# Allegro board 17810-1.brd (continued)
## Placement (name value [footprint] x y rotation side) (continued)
EC8927  SC1U50V3KX-GP  [C603H32]  122.2 108.6 0 top
EC8928  SC1U50V3KX-GP  [C603H32]  140.59 107.84 0 top
EC8929  SC1U50V3KX-GP  [C603H32]  157.4 58.64 90 top
EC8930  SCD1U25V2KX-GP  [C402H22]  35.36 90.26 270 top
EC8931  SCD1U25V2KX-GP  [C402H22]  149.66 104.87 180 bottom
EC8932  SCD1U25V2KX-GP  [C402H22]  161.97 63.85 270 bottom
EC8933  SC2200P50V2KX-2GP  [C402H22]  75.92 52.84 0 top
EC8934  SC2200P50V2KX-2GP  [C402H22]  76.81 52.84 0 top
EC8935  SC2200P50V2KX-2GP  [C402H22]  77.67 52.84 0 top
EC8936  SCD1U25V2KX-GP  [C402H22]  78.56 52.84 0 top
EC8937  SCD1U25V2KX-GP  [C402H22]  79.43 52.83 0 top
EC8938  SCD1U25V2KX-GP  [C402H22]  80.31 52.83 0 top
EC8939  SCD1U25V2KX-GP  [C402H22]  65.71 99.53 0 top
EC8940  SCD1U25V2KX-GP  [C402H22]  167.56 89.5 90 bottom
EC8941  SCD1U25V2KX-GP  [C402H22]  153.08 52.04 180 top
EC8942  SCD1U25V2KX-GP  [C402H22]  166.8 87.47 270 top
EC8943  SCD1U25V2KX-GP  [C402H22]  159.69 70.07 180 top
EC8944  SCD1U25V2KX-GP  [C402H22]  169.34 52.92 90 top
EC8945  SCD1U25V2KX-GP  [C402H22]  44.12 98.9 90 top
EC8946  SCD1U25V2KX-GP  [C402H22]  162.23 80.74 270 top
EC8947  SCD1U25V2KX-GP  [C402H22]  51.48 99.79 90 top
EC8948  SCD1U25V2KX-GP  [C402H22]  71.93 99.03 0 top
EC8949  SCD1U25V2KX-GP  [C402H22]  171.88 79.85 90 top
EC8950  SCD1U25V2KX-GP  [C402H22]  163.5 70.96 90 bottom
EC8951  SCD1U25V2KX-GP  [C402H22]  162.61 80.61 90 bottom
EC8952  SCD1U25V2KX-GP  [C402H22]  164.51 103.72 90 bottom
EC8953  SCD1U25V2KX-GP  [C402H22]  174.04 28.92 90 bottom
EC8954  SCD1U25V2KX-GP  [C402H22]  167.56 88.74 90 bottom
EC8955  SCD1U25V2KX-GP  [C402H22]  157.02 107.66 0 top
ED401  AZ5725-01FDR7G-GP  [SOD882-10D6-1H20]  131.11 75.15 270 bottom
ED501  AZ5725-01FDR7G-GP  [SOD882-10D6-1H20]  88.44 17.36 90 top
ED1217  AZ5725-01FDR7G-GP  [SOD882-10D6-1H20]  48.61 60.29 0 top
ED1302  AZ5725-01FDR7G-GP  [SOD882-10D6-1H20]  47.72 60.29 0 top
ED1701  AZ5725-01FDR7G-GP  [SOD882-10D6-1H20]  133.91 77.31 0 bottom
ED1702  AZ5725-01FDR7G-GP  [SOD882-10D6-1H20]  123.49 37.94 270 top
ED1703  AZ5725-01FDR7G-GP  [SOD882-10D6-1H20]  113.49 22.14 270 bottom
ED1704  AZ5725-01FDR7G-GP  [SOD882-10D6-1H20]  103.1 20.03 0 bottom
ED1705  AZ5725-01FDR7G-GP  [SOD882-10D6-1H20]  149.91 16.22 180 top
ED1708  AZ5725-01FDR7G-GP  [SOD882-10D6-1H20]  104.24 93.82 0 bottom
ED1709  AZ5725-01FDR7G-GP  [SOD882-10D6-1H20]  106.6 95.47 0 bottom
ED1711  AZ5725-01FDR7G-GP  [SOD882-10D6-1H20]  103.96 20.03 0 bottom
ED2401  AZ5725-01FDR7G-GP  [SOD882-10D6-1H20]  189.23 39.69 180 bottom
ED2901  DF2B6D8E-1-GP  [D1608AK-UH28]  16.43 12.34 0 top
ED2902  AZ5725-01FDR7G-GP  [SOD882-10D6-1H20]  17.19 10.41 180 bottom
ED2903  AZ5725-01FDR7G-GP  [SOD882-10D6-1H20]  16.97 22.29 90 top
ED2904  AZ5725-01FDR7G-GP  [SOD882-10D6-1H20]  17.37 23.44 90 top
ED2905  AZ5725-01FDR7G-GP  [SOD882-10D6-1H20]  18.18 24.55 90 top
ED2906  DF2B6D8E-1-GP  [D1608AK-UH28]  18.21 12.34 0 top
ED3601  L05ESDL5V0NA-4-GP  [SLP2510P8-1H22]  19.41 53.31 90 top
ED3602  AZC099-04S-1-GP  [SOT-6H58]  20.32 53.23 90 bottom
ED3603  L05ESDL5V0NA-4-GP  [SLP2510P8-1H22]  19.23 31.08 90 top
ED3801  AZ5315-02F-GP  [SOT883-1D0-321H20]  19.61 41.88 90 top
ED3802  L05ESDL5V0NA-4-GP  [SLP2510P8-1H22]  14.35 98.52 90 top
ED3803  AZ5315-02F-GP  [SOT883-1D0-321H20]  16.56 95.98 180 top
ED3804  AZ5315-02F-GP  [SOT883-1D0-321H20]  16.71 93.72 270 top
ED3805  AZ5315-02F-GP  [SOT883-1D0-321H20]  13.99 94.45 270 top
ED3806  L05ESDL5V0NA-4-GP  [SLP2510P8-1H22]  14.3 91.84 90 top
ED6305  PESD5V0U1BL-GP-U1  [SOD882-10D6-1H20]  197.28 24.1 0 top
ED6401  PESD5V0S1BB-GP-U  [SOD-523-2H26]  67.74 8.4 180 bottom
ED6402  PESD5V0S1BB-GP-U  [SOD-523-2H26]  54.53 3.52 180 bottom
EL2901  HCB1005KF-121T20-GP  [L402H24]  18.59 8.22 270 top
EL2902  HCB1005KF-121T20-GP  [L402H24]  18.21 9.64 270 top
EL2903  HCB1005KF-121T20-GP  [L402H24]  18.21 4.41 270 top
EL2904  HCB1005KF-121T20-GP  [L402H24]  17.32 3.01 270 top
EL3605  COIL-90OHM-100MHZ-5-GP  [L125100-4P-4H24]  22.4 50.23 90 bottom
EL3606  COIL-90OHM-100MHZ-5-GP  [L125100-4P-4H24]  24.1 52.34 90 bottom
EL3801  COIL-90OHM-100MHZ-5-GP  [L125100-4P-4H24]  37.36 36.08 180 top
EL3802  COIL-90OHM-100MHZ-5-GP  [L125100-4P-4H24]  45.34 37.13 90 top
EL4301  0R5J-5-GP  [R805H24]  22.78 84.17 0 top
EL4302  0R5J-5-GP  [R805H24]  24.69 84.17 0 top
EL4303  0R5J-5-GP  [R805H24]  17.19 81.65 270 top
EL4304  0R5J-5-GP  [R805H24]  17.19 79.85 270 top
EL5501  COIL-90OHM-100MHZ-5-GP  [L125100-4P-4H24]  64.95 91.53 180 top
EL5502  COIL-90OHM-100MHZ-5-GP  [L125100-4P-4H24]  73.2 92.19 180 top
EL6601  COIL-90OHM-100MHZ-5-GP  [L125100-4P-4H24]  172.29 49.98 0 top
EL6602  COIL-90OHM-100MHZ-5-GP  [L125100-4P-4H24]  172.29 47.35 0 top
EL6603  COIL-90OHM-100MHZ-5-GP  [L125100-4P-4H24]  172.41 52.44 0 top
F5501  POLYSW-1D1A6V-9-GP-U  [POLYSW-2114H30]  69.14 98.52 0 top
F5502  POLYSW-1D1A6V-9-GP-U  [POLYSW-2114H30]  55.88 99.2 180 top
F5503  POLYSW-1D1A24V-GP-U  [POLYSW-4633-UH43]  74.73 97.12 0 top
F5504  POLYSW-1D1A6V-9-GP-U  [POLYSW-2114H30]  56.79 96.21 270 top
F5701  POLYSW-1D1A6V-9-GP-U  [POLYSW-2114H30]  21.94 58.46 270 top
F6501  POLYSW-1D1A6V-9-GP-U  [POLYSW-2114H30]  151.56 10.63 90 bottom
FAN1  ACES-CON4-29-GP  [50224-0040N-001]  159.96 75.71 270 bottom
G1801  GAP-OPEN  [CON2O-U]  74.73 16.7 270 top
GMR1  HGDEDM013A-GP  [OPLGA4-0913H22]  7.26 85.48 180 top
GPU1  UNI-CONN48-6R-GP-U2  [XBGCB5009-U2]  174.7 89.86 270 bottom
GPU2  UNI-CONN28-6R-GP-U  [XBGCB5008]  174.7 75.98 90 bottom
H2  HOLE335R178-GP  [HOLE335R178]  175.7 101.21 180 bottom
H3  HOLE335R229-GP  [HOLE335R229]  162 39.06 180 bottom
H4  HOLE335R178-GP  [HOLE335R178]  188.47 21.41 180 bottom
H5  HOLE335R229-GP  [HOLE335R229]  115.9 3.99 180 bottom
H6  HOLE335R229-GP  [HOLE335R229]  25.9 3.99 180 bottom
H7  HOLE335R178-GP  [HOLE335R178]  128.85 84.21 180 bottom
H8  HOLE335R178-GP  [HOLE335R178]  102.85 84.21 180 bottom
H9  HOLE335R178-GP  [HOLE335R178]  128.85 29.21 180 bottom
H10  HOLE335R178-GP  [HOLE335R178]  102.85 29.21 180 bottom
HDA27  ALC3253-VA3-CG-GP  [QFN48J6-G465H40]  23.75 17.11 270 top
HDD1  FOX-CON20-1-GP-U1  [GS12201-1011-9H]  180.52 19.83 90 bottom
HDMI1  SKT-HDMI23-167-GP-U  [SKT-HDMI23-188137-4]  4.6 74.58 90 bottom
HPMIC1  AUDIO-JK522-GP  [AJ3R2D-Y050-412]  4.2 17.09 90 bottom
HS1  STF217R115H101-2-GP  [STF217R115H101]  10.8 86.51 180 bottom
HS2  STFSR158R113H62-GP  [STFSR158R113H62]  174.7 89.86 0 top
HS3  STFSR158R113H62-GP  [STFSR158R113H62]  174.7 75.98 0 top
IOBD1  IPEX-CON50-1-GP  [20455-050E-76]  171.7 46.46 270 bottom
KB1  PTWO-CON30-18-GP  [196528-30041-3]  83.72 6.21 180 bottom
KBBL1  ACES-CON4-90-GP-U  [50698-00401-W01-U]  105.76 4.31 180 bottom
KBC24  MEC1416-NU-D0-GP  [TQFP128-2H48]  191.01 36.44 270 top
L3801  BLM15AX221SN1D-GP  [L402H22]  25.25 61.69 90 top
LCD1  IPEX-CON40-3-GP  [20455-040E-12]  88.7 97.71 0 bottom
LED1  ACES-CON4-66-GP  [50524-00401-001]  60.94 7.61 180 bottom
NOREF  -  []  -24.49 -18.4 0 top
NOREF#2  -  []  46.07 3.73 0 top
NOREF#3  -  [unnamed#2]  234.17 -111.51 0 top
NOREF#4  -  []  136.83 94.71 0 top
NOREF#5  -  [unnamed#2]  207.95 -110.43 0 top
NOREF#6  -  [unnamed#2]  234.17 78.88 0 top
NOREF#7  -  []  226.91 47.72 0 top
NOREF#8  -  [unnamed#2]  24.4 108.43 180 top
NOREF#9  -  []  130.55 110.71 0 top
NOREF#10  -  [unnamed#2]  -1.83 109.52 0 top
NOREF#11  -  []  8.38 114.65 180 top
NOREF#12  -  []  1.7 -16.29 0 top
NOREF#13  -  [unnamed#2]  4.44 4 0 top
NOREF#14  -  []  238.35 95.88 270 top
NOREF#15  -  []  218.92 -116.72 0 top
NOREF#16  -  []  82.45 78.17 0 top
NOREF#17  -  []  159.95 -115.38 180 top
NOREF#18  -  [unnamed#2]  233.6 15.21 180 top
NOREF#19  -  [unnamed#2]  -1.22 -25.43 0 top
NOREF#20  *  [unnamed#2]  18.76 109.51 0 top
NOREF#21  -  [unnamed#2]  -1.82 -80.88 0 top
NOREF#22  -  []  1.7 -16.29 0 top
NOREF#23  -  [unnamed#2]  169.35 102.57 0 top
NOREF#24  -  []  1.7 -16.29 0 top
NOREF#25  *  [unnamed#2]  229.22 -111.51 0 top
NOREF#26  -  []  10.06 -11.34 270 top
NOREF#27  -  []  72.4 113.39 0 top
NOREF#28  *  [unnamed#2]  4.88 7.66 0 top
NOREF#29  *  [unnamed#2]  198.3 7.71 0 top
NOREF#30  -  []  1.7 -16.29 0 top
NOREF#31  -  []  5.44 -49.72 180 top
NOREF#32  -  []  182.85 -4.96 180 top
NOREF#33  *  [unnamed#2]  232.84 113.08 0 top
NOREF#34  *  [unnamed#2]  18.76 109.51 180 bottom
NOREF#35  -  []  86.92 26.25 180 bottom
NOREF#36  -  []  86.28 105.38 180 bottom
NOREF#37  -  []  10.06 -28.1 90 bottom
NOREF#38  *  [unnamed#2]  203.12 7.89 180 bottom
NOREF#39  -  []  218.24 17.62 180 bottom
NOREF#40  -  []  18.97 -19.08 180 bottom
NOREF#41  -  []  178.1 46.07 180 bottom
NOREF#42  *  [unnamed#2]  17.24 99.2 180 bottom
NOREF#43  *  [unnamed#2]  136.4 16.04 180 bottom
NOREF#44  -  []  38.4 78.45 180 bottom
NOREF#45  *  [unnamed#2]  95.25 89.35 180 bottom
NOREF#46  *  [unnamed#2]  229.22 -111.51 180 bottom
NOREF#47  *  [unnamed#2]  4.88 7.64 180 bottom
NOREF#48  *  [unnamed#2]  232.84 113.08 180 bottom
NOREF#49  -  []  94.41 111.85 180 bottom
PC1001  SC22U6D3V3MX-1-GP  [C603H40]  126.13 97.73 180 top
PC1002  SC22U6D3V3MX-1-GP  [C603H40]  139.75 76.04 270 bottom
PC1003  SC22U6D3V3MX-1-GP  [C603H40]  140 63.97 0 top
PC1004  SC22U6D3V3MX-1-GP  [C603H40]  141.27 69.31 180 top
PC1005  SC22U6D3V3MX-1-GP  [C603H40]  119.56 56.73 0 top
PC1006  SC22U6D3V3MX-1-GP  [C603H40]  113.87 60.67 180 top
PC1007  SC22U6D3V3MX-1-GP  [C603H40]  139.5 71.21 90 top
PC1008  SC22U6D3V3MX-1-GP  [C603H40]  139.5 76.29 90 top
PC1009  SC22U6D3V3MX-1-GP  [C603H40]  132.76 62.7 180 bottom
PC1010  SC22U6D3V3MX-1-GP  [C603H40]  113.59 53.66 180 top
PC1011  SC22U6D3V3MX-1-GP  [C603H40]  113.21 56.73 0 top
PC1012  SC22U6D3V3MX-1-GP  [C603H40]  115.62 53.66 180 top
PC1013  SC22U6D3V3MX-1-GP  [C603H40]  117.65 53.66 180 top
PC1014  SC22U6D3V3MX-1-GP  [C603H40]  114.48 56.73 0 top
PC1015  SC22U6D3V3MX-1-GP  [C603H40]  115.14 60.67 180 top
PC1016  SC22U6D3V3MX-1-GP  [C603H40]  119.68 53.66 180 top
PC1017  SC22U6D3V3MX-1-GP  [C603H40]  111.94 55.72 0 top
PC1018  SC22U6D3V3MX-1-GP  [C603H40]  135.3 62.7 180 bottom
PC1019  SC22U6D3V3MX-1-GP  [C603H40]  134.03 62.7 180 bottom
PC1020  SC22U6D3V3MX-1-GP  [C603H40]  117.68 63.75 0 top
PC1021  SC22U6D3V3MX-1-GP  [C603H40]  139.5 77.56 90 top
PC1022  SC22U6D3V3MX-1-GP  [C603H40]  141.53 62.7 0 top
PC1023  SC22U6D3V3MX-1-GP  [C603H40]  137.29 63.97 0 top
PC1024  SC22U6D3V3MX-1-GP  [C603H40]  116.41 60.67 180 top
PC1025  SC22U6D3V3MX-1-GP  [C603H40]  117.68 60.67 180 top
PC1026  SC22U6D3V3MX-1-GP  [C603H40]  138.61 63.97 0 top
PC1027  SC22U6D3V3MX-1-GP  [C603H40]  139.75 77.44 270 bottom
PC1028  SC22U6D3V3MX-1-GP  [C603H40]  139.5 73.75 90 top
PC1029  SC22U6D3V3MX-1-GP  [C603H40]  139.5 75.02 90 top
PC1030  SC22U6D3V3MX-1-GP  [C603H40]  139.5 72.48 90 top
PC1031  SC22U6D3V3MX-1-GP  [C603H40]  141.53 62.7 180 bottom
PC1032  SC22U6D3V3MX-1-GP  [C603H40]  142.92 62.7 180 bottom
PC1033  SC22U6D3V3MX-1-GP  [C603H40]  115.14 63.75 0 top
PC1034  SC22U6D3V3MX-1-GP  [C603H40]  142.92 62.7 0 top
PC1035  SC22U6D3V3MX-1-GP  [C603H40]  115.75 56.73 0 top
PC1036  SC22U6D3V3MX-1-GP  [C603H40]  142.54 68.93 180 top
PC1037  SC22U6D3V3MX-1-GP  [C603H40]  118.92 68.42 270 top
PC1038  SC22U6D3V3MX-1-GP  [C603H40]  119.3 76.29 90 top
PC1039  SC22U6D3V3MX-1-GP  [C603H40]  123.59 97.73 180 top
PC1040  SC22U6D3V3MX-1-GP  [C603H40]  133.78 89.37 180 bottom
PC1041  SC22U6D3V3MX-1-GP  [C603H40]  124.43 95.5 0 bottom
PC1042  SC22U6D3V3MX-1-GP  [C603H40]  122.22 89.88 180 bottom
PC1043  SC22U6D3V3MX-1-GP  [C603H40]  118.92 69.69 270 top
PC1044  SC22U6D3V3MX-1-GP  [C603H40]  115.87 70.96 90 top
PC1045  SC22U6D3V3MX-1-GP  [C603H40]  124.76 89.88 180 bottom
PC1046  SC22U6D3V3MX-1-GP  [C603H40]  119.3 73.75 90 top
PC1047  SC22U6D3V3MX-1-GP  [C603H40]  118.92 70.96 270 top
PC1048  SC22U6D3V3MX-1-GP  [C603H40]  128.57 90.14 180 bottom
PC1049  SC22U6D3V3MX-1-GP  [C603H40]  110.21 71.24 0 top
PC1050  SC22U6D3V3MX-1-GP  [C603H40]  112.7 70.96 270 top
PC1051  SC22U6D3V3MX-1-GP  [C603H40]  123.49 89.88 180 bottom
PC1052  SC22U6D3V3MX-1-GP  [C603H40]  109.7 75.28 270 top
PC1053  SC22U6D3V3MX-1-GP  [C603H40]  118.51 98.42 180 top
PC1054  SC22U6D3V3MX-1-GP  [C603H40]  112.7 67.15 270 top
PC1055  SC22U6D3V3MX-1-GP  [C603H40]  119.78 98.24 180 top
PC1056  SC22U6D3V3MX-1-GP  [C603H40]  121.05 98.24 180 top
PC1057  SC22U6D3V3MX-1-GP  [C603H40]  122.32 98.24 180 top
PC1058  SC22U6D3V3MX-1-GP  [C603H40]  112.7 69.69 270 top
PC1059  SC22U6D3V3MX-1-GP  [C603H40]  108.63 76.55 270 top
PC1060  SC22U6D3V3MX-1-GP  [C603H40]  132.51 89.37 180 bottom
PC1061  SC22U6D3V3MX-1-GP  [C603H40]  115.87 69.69 90 top
PC1062  SC22U6D3V3MX-1-GP  [C603H40]  118.92 67.15 270 top
PC1063  SC22U6D3V3MX-1-GP  [C603H40]  112.7 68.42 270 top
PC1064  SC22U6D3V3MX-1-GP  [C603H40]  125.7 95.5 0 bottom
PC1065  SC22U6D3V3MX-1-GP  [C603H40]  115.87 67.15 90 top
PC1066  SC22U6D3V3MX-1-GP  [C603H40]  127.3 90.14 180 bottom
PC1067  SC22U6D3V3MX-1-GP  [C603H40]  124.86 97.73 180 top
PC1068  SC22U6D3V3MX-1-GP  [C603H40]  127.4 97.73 180 top
PC1069  SC22U6D3V3MX-1-GP  [C603H40]  128.67 98.49 180 top
PC1070  SC22U6D3V3MX-1-GP  [C603H40]  126.03 89.88 180 bottom
PC1071  SC22U6D3V3MX-1-GP  [C603H40]  115.62 50.51 0 top
PC1072  SC22U6D3V3MX-1-GP  [C603H40]  137.08 53.81 0 top
PC1073  SC22U6D3V3MX-1-GP  [C603H40]  113.59 50.51 0 top
PC1074  SC22U6D3V3MX-1-GP  [C603H40]  116.89 50.51 0 top
PC1075  SC22U6D3V3MX-1-GP  [C603H40]  119.43 51.1 0 top
PC1076  SC22U6D3V3MX-1-GP  [C603H40]  133.15 60.16 0 bottom
PC1077  SC22U6D3V3MX-1-GP  [C603H40]  134.54 60.16 0 bottom
PC1078  SC22U6D3V3MX-1-GP  [C603H40]  118.16 50.51 0 top
PC1079  SC22U6D3V3MX-1-GP  [C603H40]  117.02 56.73 0 top
PC1080  SC22U6D3V3MX-1-GP  [C603H40]  116.41 63.75 0 top
PC1081  SC22U6D3V3MX-1-GP  [C603H40]  118.29 56.73 0 top
PC1082  SC22U6D3V3MX-1-GP  [C603H40]  113.87 63.75 0 top
PC1083  SC22U6D3V3MX-1-GP  [C603H40]  108.89 90.9 90 bottom
PC1085  SC22U6D3V3MX-1-GP  [C603H40]  115.87 68.42 90 top
PC1101  SC22U6D3V3MX-1-GP  [C603H40]  81.88 67.18 180 top
PC1102  SC22U6D3V3MX-1-GP  [C603H40]  112.04 64.08 90 top
PC1103  SC22U6D3V3MX-1-GP  [C603H40]  110.16 53.2 270 top
PC1104  SC22U6D3V3MX-1-GP  [C603H40]  111.94 65.88 90 top
PC1105  SC22U6D3V3MX-1-GP  [C603H40]  95.25 18.66 270 bottom
PC1106  SC22U6D3V3MX-1-GP  [C603H40]  95.25 17.39 270 bottom
PC1107  SC10U6D3V3MX-GP  [C603H38]  83.72 60.74 0 top
PC1108  SC10U6D3V3MX-GP  [C603H38]  82.39 60.74 0 top
PC1109  SC10U6D3V3MX-GP  [C603H38]  83.44 52.84 0 top
PC1110  SCD1U25V2KX-GP  [C402H22]  82.17 52.84 0 top
PC1111  SCD1U25V2KX-GP  [C402H22]  81.28 52.84 0 top
PC1112  SCD1U25V2KX-GP  [C402H22]  81.16 60.8 0 top
PC1113  SCD1U25V2KX-GP  [C402H22]  84.03 66.83 180 top
PC1114  SC22U6D3V3MX-1-GP  [C603H40]  80.49 67.18 180 top
PC1115  SC22U6D3V3MX-1-GP  [C603H40]  50.95 48.84 270 top
PC4301  SC1U50V3KX-GP  [C603H32]  21.54 76.24 0 top
PC4302  SCD1U50V3KX-GP  [C603H36]  22.83 76.24 0 top
PC4303  SCD01U50V2KX-1GP  [C402H22]  27 85.89 270 top
PC4304  SCD01U50V2KX-1GP  [C402H22]  27 86.73 270 top
PC4305  SCD01U50V2KX-1GP  [C402H22]  27 87.57 270 top
PC4306  SC10U25V3MX-GP  [C603H40]  26.92 84.85 270 top
PC4307  SC1KP50V2KX-1DLGP  [C402H22]  24.05 83.81 270 bottom
PC4310  SC100P50V2JN-3GP  [C402H22]  39.42 72.41 90 top
PC4311  SC100P50V2JN-3GP  [C402H22]  36.35 73.91 270 top
PC4312  SCD1U25V2KX-GP  [C402H22]  48.13 83.07 270 top
PC4313  SCD1U25V2KX-GP  [C402H22]  43.51 90.8 270 top
PC4314  SC1U25V2KX-2-GP  [C402H22]  46.15 74.11 180 top
PC4315  SC100P50V2JN-3GP  [C402H22]  44.88 76.67 90 top
PC4402  SCD1U25V2KX-GP  [C402H22]  147.39 33.9 0 bottom
PC4403  SC2200P50V2KX-2GP  [C402H22]  144.96 34.31 270 top
PC4404  SC2200P50V2KX-2GP  [C402H22]  145.24 35.12 270 top
PC4405  SC10U25V5KX-GP  [C805H56]  139.11 49.27 90 bottom
PC4406  SC10U25V5KX-GP  [C805H56]  140.18 45.58 180 bottom
PC4407  SC10U25V5KX-GP  [C805H56]  138.38 46.22 180 bottom
PC4408  SC10U25V5KX-GP  [C805H56]  139.11 51.15 90 bottom
PC4409  SCD1U25V2KX-GP  [C402H22]  141.48 46.22 180 bottom
PC4410  SC2200P50V2KX-2GP  [C402H22]  142.24 46.22 180 bottom
PC4411  SCD1U25V2KX-GP  [C402H22]  141.48 46.32 0 top
PC4412  SC1U50V3KX-1-GP  [C603H36]  144.14 40.05 0 bottom
PC4413  SC2D2U10V2KX-GP  [C402H22]  147.19 31.82 270 bottom
PC4414  SCD22U25V3KX-GP  [C603H40]  145.16 39.84 0 top
PC4415  SC10U25V5KX-GP  [C805H56]  156.18 32.38 270 bottom
PC4416  SCD1U50V3KX-GP  [C603H36]  156.08 37.53 270 bottom
PC4417  SC10U25V3MX-GP  [C603H40]  156.08 38.8 270 bottom
PC4418  SC10U25V5KX-GP  [C805H56]  155.95 34.18 270 bottom
PC4419  SCD1U25V2KX-GP  [C402H22]  153.72 27.02 90 bottom
PC4420  SCD1U25V2KX-GP  [C402H22]  141.22 39.77 270 top
PC4421  SC2200P50V2KX-2GP  [C402H22]  142.59 36.39 90 top
PC4422  SC2200P50V2KX-2GP  [C402H22]  141.78 34.46 0 top
PC4423  SC2200P50V2KX-2DLGP  [C402H22]  143.31 30.32 0 bottom
PC4424  SC2200P50V2KX-2GP  [C402H22]  142.42 30.32 0 bottom
PC4426  SCD22U25V3KX-GP  [C603H40]  148.79 36.41 90 bottom
PC4427  SC560P50V2KX-2GP  [C402H24]  137.49 32.78 90 bottom
PC4428  SC1U10V2KX-1GP  [C402H22]  142.14 38.83 270 top
PC4430  SC2200P50V2KX-2GP  [C402H22]  141.3 28.36 270 bottom
PC4431  SC1U10V2KX-1GP  [C402H22]  142.95 40.94 270 top
PC4432  SCD022U16V2KX-3DLGP  [C402H22]  137.49 33.6 90 bottom
PC4433  SC10U25V5KX-GP  [C805H56]  155.95 35.98 270 bottom
PC4434  SC2200P50V2KX-2GP  [C402H22]  156.36 50.61 90 top
PC4435  SC10U25V5KX-GP  [C805H56]  153.31 32.38 90 bottom
PC4436  SC1KP50V2KX-1GP  [C402H22]  148.64 35.4 0 top
PC4437  SC1KP50V2KX-1GP  [C402H22]  146.66 37.76 0 bottom
PC4438  SC1U10V2KX-1GP  [C402H22]  136.19 30.32 0 bottom
PC4501  SCD1U25V2KX-1-DL-GP  [C402H22]  160.65 62.35 270 bottom
PC4502  SC10U25V3MX-GP  [C603H40]  157.4 58.26 90 bottom
PC4503  SC10U25V3MX-GP  [C603H40]  157.4 60.8 90 bottom
PC4504  SC10U25V3MX-GP  [C603H40]  157.4 59.53 90 bottom
PC4505  SC10U25V3MX-GP  [C603H40]  93.19 107.03 0 top
PC4506  SCD1U25V2KX-1-DL-GP  [C402H22]  158.04 55.31 180 bottom
PC4507  SC4D7U25V5KX-DL-GP  [C805H54]  164.54 56.61 0 bottom
PC4508  SCD1U25V2KX-1-DL-GP  [C402H22]  163.32 62.68 0 bottom
PC4509  SC22U6D3V3MX-1-DL-GP  [C603H40]  160.93 47.51 180 bottom
PC4510  SC22U6D3V3MX-1-DL-GP  [C603H40]  157 51.53 90 bottom
PC4511  SC22U6D3V3MX-1-DL-GP  [C603H40]  164.54 47.51 180 bottom
PC4512  SC22U6D3V3MX-1-DL-GP  [C603H40]  159.13 47.51 180 bottom
PC4513  SCD1U16V2KX-3DLGP  [C402H22]  157.21 53.18 90 bottom
PC4514  SC22U6D3V3MX-1-DL-GP  [C603H40]  109.52 110.46 0 bottom
PC4515  SC22U6D3V3MX-1-DL-GP  [C603H40]  110.41 100.68 180 bottom
PC4516  SC22U6D3V3MX-1-DL-GP  [C603H40]  110.79 110.46 0 bottom
PC4517  SC22U6D3V3MX-1-DL-GP  [C603H40]  113.33 110.46 0 bottom
PC4518  SCD1U16V2KX-3DLGP  [C402H22]  114.73 109.19 270 bottom
PC4519  SC10U25V3MX-GP  [C603H40]  94.59 107.03 0 top
PC4520  SC4D7U25V5KX-DL-GP  [C805H54]  105.84 101.18 270 bottom
PC4521  SCD1U25V2KX-1-DL-GP  [C402H22]  102.77 108.37 0 top
PC4522  SCD1U25V2KX-1-DL-GP  [C402H22]  95.98 107.15 0 top
PC4523  SC10U25V3MX-GP  [C603H40]  91.79 107.03 0 top
PC4524  SC2D2U10V3KX-1DLGP-U  [C603H36]  102.59 102.1 0 top
PC4525  SC22U6D3V3MX-1-DL-GP  [C603H40]  162.74 47.51 180 bottom
PC4526  SC1KP50V2KX-1DLGP  [C402H22]  99.62 102.33 0 top
PC4527  SC22U6D3V3MX-1-DL-GP  [C603H40]  109.02 100.68 180 bottom
PC4528  SCD1U16V2KX-3DLGP  [C402H22]  114.73 109.95 270 bottom
PC4529  SC22U6D3V3MX-1-DL-GP  [C603H40]  112.06 110.46 0 bottom
PC4530  SCD1U25V2KX-1-DL-GP  [C402H22]  94.29 103.22 0 top
PC4531  SCD1U25V2KX-1-DL-GP  [C402H22]  96.82 100.17 90 top
PC4532  SCD1U25V2KX-1-DL-GP  [C402H22]  164.16 62.17 0 bottom
PC4533  SC1KP50V2KX-1DLGP  [C402H22]  164.23 59.55 0 bottom
PC4601  SC1500P50V2KX-2-DL-GP  [C402H22]  154.61 100.55 90 top
PC4602  SCD015U25V2KX-DLGP  [C402H22]  162.05 94.96 90 bottom
PC4603  SC1KP50V2KX-1DLGP  [C402H22]  162.08 93.31 90 bottom
PC4604  SC15P50V2JN-DL-GP  [C402H22]  159.66 94.45 90 top
PC4605  SC1KP50V2KX-1DLGP  [C402H22]  163.37 92.88 0 bottom
PC4606  SCD01U50V2KX-1DLGP  [C402H22]  161.34 97.12 0 bottom
PC4607  SCD01U50V2KX-1DLGP  [C402H22]  162.1 97.32 0 bottom
PC4608  SC1KP50V2KX-1DLGP  [C402H22]  162.08 91.61 90 bottom
PC4609  SC220P50V2KX-3DLGP  [C402H22]  161.72 97.25 180 top
PC4610  SCD1U25V2KX-1-DL-GP  [C402H22]  160.07 102.61 270 bottom
PC4611  SC1KP50V2KX-1DLGP  [C402H22]  160.78 89.22 180 bottom
PC4612  SC2200P50V2KX-2DLGP  [C402H22]  159.15 89.22 0 bottom
PC4613  SC470P50V2KX-3DLGP  [C402H22]  157.78 97.63 0 top
PC4614  SC470P50V2KX-3DLGP  [C402H22]  158.93 88.74 0 top
PC4615  SC470P50V2KX-3DLGP  [C402H22]  157.69 92.35 0 top
PC4616  SCD015U25V2KX-DLGP  [C402H22]  154.86 100.93 90 bottom
PC4617  SC10P50V2JN-4DLGP  [C402H22]  157.63 89.17 270 top
PC4618  SC2200P50V2KX-2DLGP  [C402H22]  156.26 88.74 180 top
PC4619  SC15P50V2JN-DL-GP  [C402H22]  154.34 98.04 0 top
PC4620  SC470P50V2KX-3DLGP  [C402H22]  156.24 88.75 90 bottom
PC4621  SC330P50V2KX-3-DL-GP  [C402H22]  156.24 89.52 90 bottom
PC4622  SC3300P50V2KX-1DLGP  [C402H22]  153.72 100.55 0 bottom
PC4623  SCD047U25V2KX-4-GP  [C402H22]  154.99 89.88 270 top
PC4625  SC1KP50V2KX-1DLGP  [C402H22]  152.12 101.74 90 bottom
PC4627  SC1KP50V2KX-1DLGP  [C402H22]  150.95 102.12 0 bottom
PC4628  SCD1U25V2KX-1-DL-GP  [C402H22]  153.08 98.31 90 top
PC4629  SCD01U50V2KX-1DLGP  [C402H22]  153.54 91.57 90 top
PC4630  SCD1U25V2KX-1-DL-GP  [C402H22]  155.07 92.71 180 top
PC4631  SC1U10V2KX-1DLGP  [C402H22]  153.8 92.4 90 top
PC4632  SC1KP50V2KX-1DLGP  [C402H22]  159.66 95.27 270 top
PC4633  SC1KP50V2KX-1DLGP  [C402H22]  155.5 97.88 0 top
PC4634  SCD015U25V2KX-DLGP  [C402H22]  154.86 100.17 90 bottom
PC4641  SCD047U25V2KX-4-GP  [C402H22]  153.72 89.02 270 bottom
PC4646  SCD01U50V2KX-1DLGP  [C402H22]  155.93 92.7 180 top
PC4647  SC2200P50V2KX-2DLGP  [C402H22]  154.35 101.69 270 bottom
PC4648  SC2200P50V2KX-2DLGP  [C402H22]  163.37 96.99 0 bottom
PC4702  SC10U25V5KX-DL-GP  [C805H58]  159.56 70.25 0 bottom
PC4703  SC10U25V5KX-DL-GP  [C805H58]  161.87 66.29 180 bottom
PC4704  SC10U25V5KX-DL-GP  [C805H58]  157.68 70.24 0 bottom
PC4705  SC10U25V5KX-DL-GP  [C805H58]  159.97 66.29 180 bottom
PC4706  SCD22U25V3KX-DL-GP  [C603H36]  157.81 66.06 90 bottom
PC4707  SC2D2U10V3KX-1DLGP-U  [C603H36]  149.15 63.47 90 bottom
PC4708  SC1U10V2KX-1DLGP  [C402H22]  150.09 62.2 90 bottom
PC4709  SC2200P50V2KX-2DLGP  [C402H22]  152.7 70.83 90 top
PC4710  SCD1U25V2KX-1-DL-GP  [C402H22]  156.26 70.39 0 bottom
PC4721  SC2D2U10V3KX-1DLGP-U  [C603H36]  149.4 78.07 90 bottom
PC4722  SCD22U25V3KX-DL-GP  [C603H36]  157.4 82.31 90 bottom
PC4723  SC10U25V5KX-DL-GP  [C805H58]  161.42 82.52 180 bottom
PC4724  SC10U25V5KX-DL-GP  [C805H58]  161.42 85.82 0 bottom
PC4725  SC10U25V5KX-DL-GP  [C805H58]  159.56 82.52 180 bottom
PC4726  SC10U25V5KX-DL-GP  [C805H58]  157.76 85.82 0 bottom
PC4727  SC2200P50V2KX-2DLGP  [C402H22]  151.2 85.31 90 top
PC4728  SC1U10V2KX-1DLGP  [C402H22]  152.37 78.45 270 bottom
PC4729  SC10U25V5KX-DL-GP  [C805H58]  159.59 85.82 0 bottom
PC4730  SCD1U25V2KX-1-DL-GP  [C402H22]  156.46 85.89 0 bottom
PC4802  SC10U25V5KX-DL-GP  [C805H58]  147.8 96.1 270 bottom
PC4803  SC10U25V5KX-DL-GP  [C805H58]  147.24 93.69 180 bottom
PC4804  SC10U25V5KX-DL-GP  [C805H58]  147.8 97.91 270 bottom
PC4805  SC10U25V5KX-DL-GP  [C805H58]  147.8 99.71 270 bottom
PC4806  SC10U25V5KX-DL-GP  [C805H58]  143.08 99.13 90 bottom
PC4807  SC2D2U10V3KX-1DLGP-U  [C603H36]  139.37 89.88 90 bottom
PC4808  SC1U10V2KX-1DLGP  [C402H22]  141.4 89.5 270 bottom
PC4809  SCD22U25V3KX-DL-GP  [C603H36]  146.2 91.61 90 bottom
PC4810  SC2200P50V2KX-2GP  [C402H22]  135.1 99.13 90 bottom
PC4811  SCD1U25V2KX-1-DL-GP  [C402H22]  145.9 94.38 180 bottom
PC5001  SC2D2U10V3KX-1DLGP-U  [C603H36]  153.47 51.4 90 bottom
PC5002  SCD1U25V2KX-1-DL-GP  [C402H22]  150.29 58.96 180 bottom
PC5008  SCD22U25V3KX-DL-GP  [C603H36]  150.42 54.86 180 bottom
PC5027  SC10U25V5KX-DL-GP  [C805H58]  153.64 59.15 180 bottom
PC5029  SC10U25V5KX-DL-GP  [C805H58]  151.74 59.15 180 bottom
PC5031  SC2200P50V2KX-2DLGP  [C402H22]  148.51 55.97 90 top
PC5101  SC22U6D3V3MX-1-DL-GP  [C603H40]  33.83 2.38 90 bottom
PC5102  SCD1U16V2KX-3DLGP  [C402H22]  36.63 10.15 0 bottom
PC5103  SC22U6D3V3MX-1-DL-GP  [C603H40]  33.83 7.84 90 bottom
PC5104  SC22U6D3V3MX-1-DL-GP  [C603H40]  33.83 4.18 90 bottom
PC5105  SC22U6D3V3MX-1-DL-GP  [C603H40]  33.83 6.01 90 bottom
PC5106  SC10U25V5KX-DL-GP  [C805H58]  48.77 8.09 180 bottom
PC5107  SCD01U50V2KX-1DLGP  [C402H22]  47.29 8.22 180 bottom
PC5108  SC10U25V5KX-DL-GP  [C805H58]  49.33 5.68 90 bottom
PC5110  SC1U10V2KX-1DLGP  [C402H22]  43.36 3.01 180 bottom
PC5111  SC1U10V2KX-1DLGP  [C402H22]  41.32 10.89 180 top
PC5112  SC330P50V2KX-3-DL-GP  [C402H22]  46.4 3.01 0 bottom
PC5113  SC2D2U10V3KX-1DLGP-U  [C603H36]  42.34 2.89 180 bottom
PC5114  SC22U6D3V3MX-1-GP  [C603H40]  37.39 14.7 90 bottom
PC5115  SC10U6D3V3MX-DL-GP  [C603H36]  38.53 8.6 270 bottom
PC5116  SCD1U16V2KX-3DLGP  [C402H22]  44.52 13.25 270 bottom
PC5117  SCD1U25V2KX-1-DL-GP  [C402H22]  45.39 7.97 0 top
PC5118  SCD1U16V2KX-3DLGP  [C402H22]  38.78 9.62 270 bottom
PC5119  SCD1U16V2KX-3DLGP  [C402H22]  44.65 11.73 270 bottom
PC5120  SCD1U16V2KX-3DLGP  [C402H22]  44.65 12.49 270 bottom
PC5138  SCD1U16V2KX-3DLGP  [C402H22]  47.93 3.01 180 bottom
PC5201  SC22U6D3V3MX-1-GP  [C603H40]  134.31 10.76 90 bottom
PC5202  SC1U10V2KX-1DLGP  [C402H22]  143.94 5.55 90 top
PC5203  SC22U6D3V3MX-1-GP  [C603H40]  134.31 9.49 90 bottom
PC5204  SCD1U25V2KX-1-DL-GP  [C402H22]  143.56 4.28 0 top
PC5205  SC22U6D3V3MX-1-GP  [C603H40]  138.2 10.76 270 bottom
PC5206  SC22U6D3V3MX-1-GP  [C603H40]  138.2 9.49 270 bottom
PC5208  SCD1U25V2KX-1-DL-GP  [C402H22]  138.25 10.56 90 top
PC5209  SC10U25V5KX-DL-GP  [C805H58]  152.6 4 180 bottom
PC5210  SC10U25V5KX-DL-GP  [C805H58]  150.8 4 180 bottom
PC5211  SC10U25V5KX-DL-GP  [C805H58]  152.12 6.93 0 bottom
PC5212  SC220P50V2KX-3DLGP  [C402H22]  145.21 9.36 180 top
PC5213  SCD01U50V2KX-1DLGP  [C402H22]  143.94 6.37 90 top
PC5214  SCD1U50V3KX-DL-GP  [C603H35]  149.25 3.75 180 bottom
PC5215  SC1KP50V2KX-1DLGP  [C402H22]  143.94 7.2 270 top
PC5216  SC10U25V5KX-DL-GP  [C805H58]  150.32 6.93 0 bottom
PC5401  SC1U10V2KX-1DLGP  [C402H22]  55.17 13.3 90 top
PC5402  SC10U6D3V3MX-GP  [C603H38]  46.23 14.77 180 bottom
PC5403  SC10U6D3V3MX-DL-GP  [C603H36]  57.45 15.71 180 bottom
PC5405  SC68P50V2JN-1GP  [C402H22]  44.5 12.79 0 top
PC5406  SC4700P50V2KX-1GP  [C402H22]  55.93 11.52 0 top
PC5407  SCD1U16V2KX-3DLGP  [C402H22]  62.41 15.33 270 bottom
PC5408  SC1U10V2KX-1DLGP  [C402H22]  56.44 15.21 180 bottom
PC5409  SC1U10V2KX-1DLGP  [C402H22]  66.34 13.68 0 top
PC5410  SC1U10V2KX-1DLGP  [C402H22]  39.09 99.86 0 bottom
PC5411  SC68P50V2JN-1GP  [C402H22]  46.02 99.66 90 top
PC5412  SC10U6D3V3MX-GP  [C603H38]  48.31 101.69 0 bottom
PC5413  SC10U6D3V3MX-GP  [C603H38]  50.11 101.7 0 bottom
PC5414  SC10U6D3V3MX-DL-GP  [C603H36]  44.88 96.36 270 bottom
PC5427  SCD1U16V2KX-3DLGP  [C402H22]  40.18 95.6 180 bottom
PD4301  P6AF24A-R1-00001-GP  [D4724AKH44]  22.91 79.72 90 top
PD4302  LBAV99LT1G-1-GP  [SOT23-2D4-312H44]  16.91 70.6 180 bottom
PD4303  L30ESD24VC3-2-GP  [SOT23-2D4-312H60]  15.87 79.85 180 bottom
PD4304  SMF18A-GP  [SOD123AK-2H43]  155.83 29.61 270 bottom
PD4305  RB751V-40H-GP  [SOD323AKH38]  28.5 89.04 270 top
PD4306  RB751V-40H-GP  [SOD323AKH38]  28.5 74.49 180 top
PD4307  BAT54TM-GP  [SOD923-10D6AKH18]  24.51 90.39 270 top
PD4308  BAT54TM-GP  [SOD923-10D6AKH18]  22.15 76.12 90 bottom
PD4309  BAT54TM-GP  [SOD923-10D6AKH18]  31.32 90.85 180 top
PD4310  BAT54TM-GP  [SOD923-10D6AKH18]  33.37 91.05 270 top
PD4401  RB751VM-40TE-17-GP  [SOD323-2513AKH36]  148.84 40.28 90 bottom
PD4402  RB751VM-40TE-17-GP  [SOD323-2513AKH36]  149.48 39.74 270 top
PD4404  L1SS355T1G-GP  [SOD323AKH44]  147.19 26.79 180 bottom
PD4405  RB751VM-40TE-17-GP  [SOD323-2513AKH36]  151.12 36.03 0 bottom
PD4406  RB751VM-40TE-17-GP  [SOD323-2513AKH36]  149.91 32.94 270 bottom
PD4407  RB751VM-40TE-17-GP  [SOD323-2513AKH36]  153.38 35.25 180 bottom
PD4409  RB751V-40H-GP  [SOD323AKH38]  157.66 54.5 0 top
PD4411  RB751V-40H-GP  [SOD323AKH38]  155.6 54.48 0 top
PG4401  GAP-CLOSE-PWR-3-GP  [GAP-CLOSE-PWR-3]  141.96 30.4 270 top
PG4402  GAP-CLOSE-PWR-6-GP  [GAP-CLOSE-PWR]  39.04 85.34 0 top
PG4403  GAP-CLOSE-PWR-6-GP  [GAP-CLOSE-PWR]  39.04 87.11 0 top
PG4404  GAP-CLOSE-PWR-3-GP  [GAP-CLOSE-PWR-3]  141.73 50.99 90 top
PG4405  GAP-CLOSE-PWR-3-GP  [GAP-CLOSE-PWR-3]  141.98 51.02 90 bottom
PG4406  GAP-CLOSE-PWR-3-GP  [GAP-CLOSE-PWR-3]  141.22 51.02 90 bottom
PG4407  GAP-CLOSE-PWR-3-GP  [GAP-CLOSE-PWR-3]  140.97 50.99 90 top
PG4408  GAP-CLOSE-PWR-3-GP  [GAP-CLOSE-PWR-3]  144.79 32.66 180 top
PG4409  GAP-CLOSE-PWR-6-GP  [GAP-CLOSE-PWR]  144.98 30.4 90 top
PG4410  GAP-CLOSE-PWR-6-GP  [GAP-CLOSE-PWR]  143.89 30.4 90 top
PG4412  GAP-CLOSE-PWR-6-GP  [GAP-CLOSE-PWR]  152.07 41.62 180 bottom
PG4413  GAP-CLOSE-PWR-6-GP  [GAP-CLOSE-PWR]  152.07 40.22 180 bottom
PG4414  GAP-CLOSE-PWR-3-GP  [GAP-CLOSE-PWR-3]  141.04 30.4 270 top
PG4415  GAP-CLOSE-PWR-3-GP  [GAP-CLOSE-PWR-3]  141.27 30.24 270 bottom
PG4419  GAP-CLOSE-PWR-3-GP  [GAP-CLOSE-PWR-3]  142.87 30.4 270 top
PG4501  GAP-CLOSE-PWR-3-GP  [GAP-CLOSE-PWR-3]  94.54 109.82 270 top
PG4502  GAP-CLOSE-PWR-3-GP  [GAP-CLOSE-PWR-3]  93.78 109.82 270 top
PG4503  GAP-CLOSE-PWR-3-GP  [GAP-CLOSE-PWR-3]  93.01 109.82 270 top
PG4504  GAP-CLOSE-PWR-3-GP  [GAP-CLOSE-PWR-3]  92.25 109.82 270 top
PG4505  GAP-CLOSE-PWR-3-GP  [GAP-CLOSE-PWR-3]  91.49 109.82 270 top
PG4506  GAP-CLOSE-PWR-3-GP  [GAP-CLOSE-PWR-3]  90.73 109.82 270 top
PG4507  GAP-CLOSE-PWR-3-GP  [GAP-CLOSE-PWR-3]  114.98 106.87 0 top
PG4508  GAP-CLOSE-PWR-3-GP  [GAP-CLOSE-PWR-3]  114.98 106.11 0 top
PG4509  GAP-CLOSE-PWR-3-GP  [GAP-CLOSE-PWR-3]  114.98 105.35 0 top
PG4510  GAP-CLOSE-PWR-3-GP  [GAP-CLOSE-PWR-3]  114.98 104.59 0 top
PG4511  GAP-CLOSE-PWR-3-GP  [GAP-CLOSE-PWR-3]  114.98 106.87 0 bottom
PG4512  GAP-CLOSE-PWR-3-GP  [GAP-CLOSE-PWR-3]  114.98 106.11 0 bottom
PG4513  GAP-CLOSE-PWR-3-GP  [GAP-CLOSE-PWR-3]  114.98 105.35 0 bottom
PG4514  GAP-CLOSE-PWR-3-GP  [GAP-CLOSE-PWR-3]  114.98 104.59 0 bottom
PG4515  GAP-CLOSE-PWR-3-GP  [GAP-CLOSE-PWR-3]  157.91 62.48 270 bottom
PG4516  GAP-CLOSE-PWR-3-GP  [GAP-CLOSE-PWR-3]  157.15 62.48 270 bottom
PG4517  GAP-CLOSE-PWR-3-GP  [GAP-CLOSE-PWR-3]  159.43 62.48 270 bottom
PG4518  GAP-CLOSE-PWR-3-GP  [GAP-CLOSE-PWR-3]  158.67 62.48 270 bottom
PG4519  GAP-CLOSE-PWR-3-GP  [GAP-CLOSE-PWR-3]  164.69 50.21 0 top
PG4520  GAP-CLOSE-PWR-3-GP  [GAP-CLOSE-PWR-3]  164.69 49.45 0 top
PG4521  GAP-CLOSE-PWR-3-GP  [GAP-CLOSE-PWR-3]  164.69 50.97 0 bottom
PG4522  GAP-CLOSE-PWR-3-GP  [GAP-CLOSE-PWR-3]  164.69 50.21 0 bottom
PG4523  GAP-CLOSE-PWR-3-GP  [GAP-CLOSE-PWR-3]  164.69 49.45 0 bottom
PG4524  GAP-CLOSE-PWR-3-GP  [GAP-CLOSE-PWR-3]  164.69 50.97 0 top
PG4527  GAP-CLOSE-PWR-3-GP  [GAP-CLOSE-PWR-3]  108.13 109.82 0 bottom
PG4528  GAP-CLOSE-PWR-3-GP  [GAP-CLOSE-PWR-3]  101.45 102.63 270 top
PG4529  GAP-CLOSE-PWR-3-GP  [GAP-CLOSE-PWR-3]  93.95 105.38 0 top
PG4530  GAP-CLOSE-PWR-3-GP  [GAP-CLOSE-PWR-3]  164.21 52.16 270 bottom
PG4531  GAP-CLOSE-PWR-3-GP  [GAP-CLOSE-PWR-3]  162.84 59.76 90 top
PG4532  GAP-CLOSE-PWR-3-GP  [GAP-CLOSE-PWR-3]  162.81 58.16 90 top
PG4601  GAP-CLOSE-PWR-3-GP  [GAP-CLOSE-PWR-3]  152.58 99.91 180 top
PG4701  GAP-CLOSE-PWR-3-GP  [GAP-CLOSE-PWR-3]  163.5 67.28 0 bottom
PG4702  GAP-CLOSE-PWR-3-GP  [GAP-CLOSE-PWR-3]  163.5 68.04 0 bottom
PG4703  GAP-CLOSE-PWR-3-GP  [GAP-CLOSE-PWR-3]  163.5 68.8 0 bottom
PG4704  GAP-CLOSE-PWR-3-GP  [GAP-CLOSE-PWR-3]  163.5 69.56 0 bottom
PG4705  GAP-CLOSE-PWR-3-GP  [GAP-CLOSE-PWR-3]  163.07 83.2 0 bottom
PG4707  GAP-CLOSE-PWR-3-GP  [GAP-CLOSE-PWR-3]  146.61 67.95 0 bottom
PG4708  GAP-CLOSE-PWR-3-GP  [GAP-CLOSE-PWR-3]  144.5 67.91 180 bottom
PG4711  GAP-CLOSE-PWR-3-GP  [GAP-CLOSE-PWR-3]  144.57 82.43 180 bottom
PG4712  GAP-CLOSE-PWR-3-GP  [GAP-CLOSE-PWR-3]  146.86 82.43 0 bottom
PG4721  GAP-CLOSE-PWR-3-GP  [GAP-CLOSE-PWR-3]  163.07 83.96 0 bottom
PG4722  GAP-CLOSE-PWR-3-GP  [GAP-CLOSE-PWR-3]  163.07 85.49 0 bottom
PG4723  GAP-CLOSE-PWR-3-GP  [GAP-CLOSE-PWR-3]  163.07 84.73 0 bottom
PG4808  GAP-CLOSE-PWR-3-GP  [GAP-CLOSE-PWR-3]  135.74 94.52 0 bottom
PG4809  GAP-CLOSE-PWR-3-GP  [GAP-CLOSE-PWR-3]  133.45 94.52 180 bottom
PG5001  GAP-CLOSE-PWR-3-GP  [GAP-CLOSE-PWR-3]  154.58 61.92 180 bottom
PG5002  GAP-CLOSE-PWR-3-GP  [GAP-CLOSE-PWR-3]  154.58 61.15 180 bottom
PG5021  GAP-CLOSE-PWR-3-GP  [GAP-CLOSE-PWR-3]  140.89 57.12 0 bottom
PG5022  GAP-CLOSE-PWR-3-GP  [GAP-CLOSE-PWR-3]  138.61 57.12 180 bottom
PG5101  GAP-CLOSE-PWR-3-GP  [GAP-CLOSE-PWR-3]  50.85 4.03 90 bottom
PG5102  GAP-CLOSE-PWR-3-GP  [GAP-CLOSE-PWR-3]  35.76 9.85 90 bottom
PG5103  GAP-CLOSE-PWR-3-GP  [GAP-CLOSE-PWR-3]  51.61 4.03 90 bottom
PG5104  GAP-CLOSE-PWR-3-GP  [GAP-CLOSE-PWR-3]  51.87 4.03 90 top
PG5106  GAP-CLOSE-PWR-3-GP  [GAP-CLOSE-PWR-3]  34.24 9.21 90 top
PG5107  GAP-CLOSE-PWR-3-GP  [GAP-CLOSE-PWR-3]  50.09 4.03 90 bottom
PG5108  GAP-CLOSE-PWR-3-GP  [GAP-CLOSE-PWR-3]  50.34 4.03 90 top
PG5109  GAP-CLOSE-PWR-3-GP  [GAP-CLOSE-PWR-3]  35 9.85 90 bottom
PG5110  GAP-CLOSE-PWR-3-GP  [GAP-CLOSE-PWR-3]  51.1 4.03 90 top
PG5111  GAP-CLOSE-PWR-3-GP  [GAP-CLOSE-PWR-3]  34.24 9.85 90 bottom
PG5112  GAP-CLOSE-PWR-3-GP  [GAP-CLOSE-PWR-3]  35 9.21 90 top
PG5113  GAP-CLOSE-PWR-3-GP  [GAP-CLOSE-PWR-3]  42.85 2.63 0 top
PG5114  GAP-CLOSE-PWR-3-GP  [GAP-CLOSE-PWR-3]  35.76 9.21 90 top
PG5115  GAP-CLOSE-PWR-3-GP  [GAP-CLOSE-PWR-3]  36.52 9.21 90 top
PG5120  GAP-CLOSE-PWR-3-GP  [GAP-CLOSE-PWR-3]  39.67 14.57 0 bottom
PG5121  GAP-CLOSE-PWR-3-GP  [GAP-CLOSE-PWR-3]  39.67 15.33 0 bottom
PG5201  GAP-CLOSE-PWR-3-GP  [GAP-CLOSE-PWR-3]  137.62 11.95 90 top
PG5204  GAP-CLOSE-PWR-3-GP  [GAP-CLOSE-PWR-3]  134.57 11.95 90 top
PG5206  GAP-CLOSE-PWR-3-GP  [GAP-CLOSE-PWR-3]  137.87 12.11 90 bottom
PG5207  GAP-CLOSE-PWR-3-GP  [GAP-CLOSE-PWR-3]  135.33 11.95 90 top
PG5208  GAP-CLOSE-PWR-3-GP  [GAP-CLOSE-PWR-3]  136.85 11.95 90 top
PG5209  GAP-CLOSE-PWR-3-GP  [GAP-CLOSE-PWR-3]  136.09 11.95 90 top
PG5210  GAP-CLOSE-PWR-3-GP  [GAP-CLOSE-PWR-3]  154.23 5.1 180 bottom
PG5211  GAP-CLOSE-PWR-3-GP  [GAP-CLOSE-PWR-3]  137.11 12.11 90 bottom
PG5212  GAP-CLOSE-PWR-3-GP  [GAP-CLOSE-PWR-3]  154.23 5.86 180 bottom
PG5213  GAP-CLOSE-PWR-3-GP  [GAP-CLOSE-PWR-3]  136.35 12.11 90 bottom
PG5214  GAP-CLOSE-PWR-3-GP  [GAP-CLOSE-PWR-3]  154.23 6.62 180 bottom
PG5215  GAP-CLOSE-PWR-3-GP  [GAP-CLOSE-PWR-3]  134.82 12.11 90 bottom
PG5216  GAP-CLOSE-PWR-3-GP  [GAP-CLOSE-PWR-3]  135.58 12.11 90 bottom
PG5223  GAP-CLOSE-PWR-6-GP  [GAP-CLOSE-PWR]  143.18 9.11 180 top
PG5404  GAP-CLOSE-PWR-3-GP  [GAP-CLOSE-PWR-3]  65.07 13.45 180 top
PG5405  GAP-CLOSE-PWR-3-GP  [GAP-CLOSE-PWR-3]  43.61 15.26 180 bottom
PG5406  GAP-CLOSE-PWR-3-GP  [GAP-CLOSE-PWR-3]  43.61 16.02 180 bottom
PG5407  GAP-CLOSE-PWR-3-GP  [GAP-CLOSE-PWR-3]  43.61 14.49 180 bottom
PG5408  GAP-CLOSE-PWR-3-GP  [GAP-CLOSE-PWR-3]  50.6 99.71 0 bottom
PG5409  GAP-CLOSE-PWR-3-GP  [GAP-CLOSE-PWR-3]  50.6 98.95 0 bottom
PL4401  COIL-4D7UH-33-GP  [L7066-1830-UH119]  148.92 47.01 270 bottom
PL4501  COIL-1D5UH-43-GP  [L4947-1015H119]  161.03 52.54 180 bottom
PL4502  IND-2D2UH-46-GP-U1  [L7066-1830-UH119]  107.72 105.66 270 bottom
PL4701  COIL-D15UH-2-GP  [L7366-1930H158]  145.62 67.99 90 bottom
PL4702  COIL-D15UH-2-GP  [L7366-1930H158]  145.72 82.56 90 bottom
PL4801  COIL-D15UH-2-GP  [L7366-1930H158]  134.59 94.39 90 bottom
PL5001  IND-D47UH-22-GP-U  [L7066-1830-UH119]  139.75 57.04 90 bottom
PL5101  COIL-1UH-73-GP  [L4947-1115H119]  38.53 4.54 90 bottom
PL5201  IND-1UH-94-GP-U  [L686647-127318H119]  137.62 5.35 90 bottom
PQ4301  PJA138KA-GP  [SOT23DGS2D4H44]  16.03 75.73 180 bottom
PQ4302  PMBS3904-1-GP  [SOT-23-10H44]  22.78 73.3 270 bottom
PQ4304  LMUN5212T1G-GP  [SOT323CBE2D2H40]  19.35 77.79 0 bottom
PQ4305  LTA024EUB-FS8-GP  [SC70-2D2-312H44]  19.38 73.78 0 bottom
PQ4306  2N7002K-2-GP  [SOT23DGS2D4H44]  32.15 75.9 180 top
PQ4307  2N7002KDW-1-GP  [SOT-363H44]  36.88 70.81 90 top
PQ4308  2N7002KDW-1-GP  [SOT-363H44]  30.02 70.58 0 top
PQ4309  2N7002KDW-1-GP  [SOT-363H44]  45.79 88.84 270 top
PQ4310  2N7002KDW-1-GP  [SOT-363H44]  33.32 70.81 90 top
PQ4311  2N7002KDW-1-GP  [SOT-363H44]  42.16 88.84 90 top
PQ4312  2N7002K-2-GP  [SOT23DGS2D4H44]  43.36 70.83 90 top
PQ4313  2N7002KDW-1-GP  [SOT-363H44]  43.86 74.51 180 top
PQ4405  2N7002KDW-1-GP  [SOT-363H44]  138.38 30.04 270 bottom
PQ4408  PMBS3906-GP  [SOT-23-10H44]  144.02 27.4 270 bottom
PQ4415  2N7002KDW-1-GP  [SOT-363H44]  139.98 39.39 270 bottom
PR2455  150KR2F-L-GP  [R402H16]  196.57 40.2 270 bottom
PR4302  15KR2F-GP  [R402H16]  19.53 74.87 180 top
PR4303  10KR2J-3-GP  [R402H16]  20.5 70.93 0 bottom
PR4304  2K2R2J-2-GP  [R402H16]  15.29 73.24 270 bottom
PR4305  33R2J-2-GP  [R402H16]  17.37 74.36 90 top
PR4306  33R2J-2-GP  [R402H16]  17.37 75.33 270 top
PR4307  240KR3-GP  [R603H22]  24.1 76.24 0 top
PR4308  47KR2F-GP  [R402H16]  23.7 74.62 270 top
PR4309  100KR2J-1-GP  [R402H16]  18.64 74.87 0 top
PR4310  1KR2J-1-GP  [R402H16]  49.33 88.51 0 top
PR4311  100KR2F-L1-GP  [R402H16]  31.11 88.76 180 top
PR4312  470KR2F-GP  [R402H16]  24.56 78.07 0 bottom
PR4313  71K5R2F-1-GP  [R402H16]  23.8 78.07 180 bottom
PR4314  0R2J-2-GP  [R402H16]  24.81 73.37 0 top
PR4315  18K7R2F-GP  [R402H16]  31.98 88.76 180 top
PR4316  20KR2J-L2-GP  [R402H16]  27.02 83.81 270 top
PR4317  0R0603-PAD-1-GP-U  [0R0603-PAD-U]  17.16 78.3 270 top
PR4318  100KR2J-1-GP  [R402H16]  33.96 88.61 270 top
PR4319  100KR2F-L1-GP  [R402H16]  39.42 73.93 270 top
PR4320  240KR2F-L-GP  [R402H16]  27.66 69.51 270 top
PR4321  47KR2F-GP  [R402H16]  27.66 68.75 90 top
PR4322  10KR2F-2-GP  [R402H16]  38.15 73.19 0 top
PR4323  100KR2F-L1-GP  [R402H16]  39.17 69.94 0 top
PR4324  100KR2F-L1-GP  [R402H16]  48.49 87.88 0 top
PR4325  100KR2F-L1-GP  [R402H16]  40.44 69.43 270 top
PR4326  0R2J-2-GP  [R402H16]  24.81 89.17 270 top
PR4327  12K4R2F-GP  [R402H16]  29.89 74.64 180 top
PR4328  2K2R2J-2-GP  [R402H16]  31.16 73.42 270 top
PR4329  1MR2J-1-GP  [R402H16]  25.58 72.48 0 top
PR4330  240KR2F-L-GP  [R402H16]  46.66 85.44 0 top
PR4332  100KR2F-L1-GP  [R402H16]  35.66 72.76 90 top
PR4333  10KR2F-2-GP  [R402H16]  33.96 89.5 270 top
PR4335  100KR2J-1-GP  [R402H16]  19.51 80.18 270 bottom
PR4336  680KR2J-GP  [R402H16]  39.42 73.17 90 top
PR4337  240KR2F-L-GP  [R402H16]  39.52 89.58 180 top
PR4338  100R2512J-1-GP  [R2512H28]  38.78 76.17 270 top
PR4339  64K9R2F-1-GP  [R402H16]  48.59 84.32 180 top
PR4340  100KR2F-L1-GP  [R402H16]  42.82 91.56 90 top
PR4341  0R0402-PAD-1-GP  [0R0402-PAD]  41.83 90.8 270 top
PR4342  100KR2F-L1-GP  [R402H16]  41.1 70.88 0 top
PR4343  200KR2F-L-GP  [R402H16]  42.72 77.23 0 top
PR4344  680KR2J-GP  [R402H16]  46.15 71.44 180 top
PR4401  1KR2F-3-GP  [R402H16]  140.99 29.15 270 bottom
PR4402  D01R3721F-GP-U  [R3720H40]  36.71 86.22 180 top
PR4403  100R5F-2-GP  [R805H24]  148.51 38.24 270 bottom
PR4407  2D2R5J-1-GP  [R805H24]  145.95 40.05 0 bottom
PR4408  300KR2F-GP  [R402H16]  147.09 32.66 90 bottom
PR4409  37K4R2F-1-GP  [R402H16]  147.24 30.98 270 bottom
PR4410  1KR2F-3-GP  [R402H16]  148.64 37.05 180 top
PR4411  2R2F-GP  [R402H16]  141.65 41.09 0 top
PR4412  4D7R3F-L-GP  [R603H22]  143.28 39.92 90 top
PR4413  100KR2F-L1-GP  [R402H16]  135.74 29.07 270 bottom
PR4414  2R2F-GP  [R402H16]  149.15 35.25 90 bottom
PR4415  D01R3721F-GP-U  [R3720H40]  154.35 40.96 180 bottom
PR4416  100R2F-L1-GP-U  [R402H14]  138.73 33.19 0 bottom
PR4420  10KR2F-2-GP  [R402H16]  137.26 35.12 180 bottom
PR4421  10KR2F-2-GP  [R402H16]  138 36.95 0 bottom
PR4422  100KR2F-L2-GP  [R402H16]  144.95 33.54 270 top
PR4423  100KR2F-L1-GP  [R402H16]  140.54 32.73 90 top
PR4424  100KR2F-L1-GP  [R402H16]  139.22 37.41 270 bottom
PR4430  0R0402-PAD-1-GP  [0R0402-PAD]  140.54 33.57 90 top
PR4431  100KR2J-1-GP  [R402H16]  147.24 30.14 90 bottom
PR4433  150KR2F-L-GP  [R402H16]  139.67 32.43 180 bottom
PR4436  1MR2J-1-GP  [R402H16]  147.5 29.18 90 bottom
PR4437  49K9R2F-L-GP  [R402H16]  143.43 37.18 90 top
PR4438  10KR2F-2-GP  [R402H16]  145.95 30.32 180 bottom
PR4439  10KR2F-2-GP  [R402H16]  145.08 30.32 180 bottom
PR4442  470KR2J-L1-GP  [R402H15]  158.04 50.13 0 top
PR4443  300KR2F-L-GP  [R402H16]  143.13 33.04 90 top
PR4444  0R0402-PAD-1-GP  [0R0402-PAD]  149.15 34.46 90 bottom
PR4445  100KR2F-L2-GP  [R402H16]  144.19 30.32 180 bottom
PR4447  0R0603-PAD-1-GP-U  [0R0603-PAD-U]  146.45 39.84 180 top
PR4448  0R0402-PAD-1-GP  [0R0402-PAD]  140.84 41.09 0 top
PR4449  1KR2F-3-GP  [R402H16]  138.07 35.12 0 bottom
PR4450  10KR2F-2-GP  [R402H16]  135.43 30.32 180 bottom
PR4451  680KR2F-GP  [R402H16]  137.49 28.87 90 top
PR4455  0R0402-PAD-1-GP  [0R0402-PAD]  138.81 29.76 0 top
PR4458  0R0402-PAD-1-GP  [0R0402-PAD]  146.28 24.07 270 bottom
PR4463  0R2J-2-GP  [R402H16]  137.49 30.52 270 top
PR4471  100KR2F-L2-GP  [R402H16]  142.67 40.86 270 bottom
PR4501  0R0603-PAD-1-GP-U  [0R0603-PAD-U]  157.02 56.29 180 bottom
PR4502  0R0603-PAD-1-GP-U  [0R0603-PAD-U]  100.95 109.29 90 top
PR4503  0R2J-2-GP  [R402H16]  95.69 103.73 0 top
PR4504  0R0402-PAD-1-GP  [0R0402-PAD]  94.16 100.93 0 top
PR4505  100KR2J-1-GP  [R402H16]  161.95 59.73 180 top
PR4506  1KR2F-3-GP  [R402H16]  165.05 59.45 0 bottom
PR4507  1KR2F-3-GP  [R402H16]  98.86 102.33 180 top
PR4508  200KR2F-L1-GP  [R402H16]  162.56 62.63 0 bottom
PR4509  1KR2F-3-GP  [R402H16]  161.8 62.63 180 bottom
PR4510  100KR2J-1-GP  [R402H16]  93.78 104.49 270 top
PR4511  1KR2F-3-GP  [R402H16]  92.51 103.22 180 top
PR4512  200KR2F-L1-GP  [R402H16]  93.4 103.22 0 top
PR4513  1MR2J-1-GP  [R402H16]  96.7 100.93 90 top
PR4514  1MR2J-1-GP  [R402H16]  165 62.17 0 bottom
PR4515  0R0402-PAD-1-GP  [0R0402-PAD]  96.58 103.73 0 top
PR4516  0R0402-PAD-1-GP  [0R0402-PAD]  96.11 104.99 270 top
PR4530  0R2J-2-GP  [R402H16]  94.97 101.41 180 top
PR4551  560KR2F-GP  [R402H16]  100.38 102.33 0 top
PR4601  1KR2F-3-GP  [R402H16]  151.32 91.73 270 bottom
PR4602  1K5R2F-2-GP  [R402H16]  159.79 93.62 90 top
PR4604  0R0402-PAD-1-GP  [0R0402-PAD]  164.62 93.29 90 bottom
PR4605  825R2F-GP  [R402H16]  162.08 94.2 90 bottom
PR4606  NTC-100K-11-GP-U  [NTC-402H24-U]  139.37 61.43 90 bottom
PR4607  0R0402-PAD-1-GP  [0R0402-PAD]  164.62 92.51 90 bottom
PR4608  2K87R2F-1-GP  [R402H16]  162.07 92.45 90 bottom
PR4609  14K3R2F-GP  [R402H16]  164.51 95.34 180 bottom
PR4611  18K2R2F-L-GP  [R402H16]  159.66 96.08 270 top
PR4612  8K06R3F-AS-GP  [R603H22]  164.95 96.94 270 bottom
PR4613  91KR2F-GP  [R402H16]  160.91 97.25 180 top
PR4614  10KR2F-2-GP  [R402H16]  164.67 99.91 180 bottom
PR4616  0R0402-PAD-1-GP  [0R0402-PAD]  163.67 91.61 90 bottom
PR4617  0R0402-PAD-1-GP  [0R0402-PAD]  162.09 89.68 90 bottom
PR4618  0R0402-PAD-1-GP  [0R0402-PAD]  162.09 88.85 90 bottom
PR4619  1K54R2F-GP  [R402H16]  159.97 89.22 0 bottom
PR4621  45D3R2F-L-GP  [R402H16]  155.93 105.81 0 top
PR4622  75R2F-2-GP  [R402H16]  155.09 105.81 0 top
PR4623  100R2F-L1-GP-U  [R402H14]  158.77 102.99 180 bottom
PR4624  1KR2F-3-GP  [R402H16]  154.25 105.81 0 top
PR4625  37D4R2F-GP  [R402H16]  159.82 89.63 0 top
PR4626  1KR2F-3-GP  [R402H16]  158.52 89.98 270 top
PR4627  8K06R3F-AS-GP  [R603H22]  156.49 102.3 180 bottom
PR4628  105KR2F-1-GP  [R402H16]  158.55 97.5 0 top
PR4629  14KR2F-GP  [R402H16]  155.47 102.43 0 bottom
PR4630  0R0402-PAD-1-GP  [0R0402-PAD]  162.23 99.43 270 bottom
PR4631  4K75R2F-1-GP  [R402H16]  157.63 88.31 270 top
PR4632  28KR2F-GP  [R402H16]  156.81 92.66 0 top
PR4633  NTC-100K-11-GP-U  [NTC-402H24-U]  136.57 90.01 270 bottom
PR4634  NTC-220K-GP-U  [NTC-402H22-U]  145.97 71.97 270 bottom
PR4635  51K1R2F-GP  [R402H16]  156.26 97.88 0 top
PR4636  2K49R2F-GP  [R402H16]  157.02 97.88 0 top
PR4637  75KR3F-GP  [R603H22]  152.83 88.36 0 top
PR4638  200KR2F-L-GP  [R402H16]  156.16 87.98 90 bottom
PR4639  75KR2F-GP  [R402H16]  157.38 88.66 0 bottom
PR4640  20K5R2F-GP  [R402H16]  158.15 89.01 0 bottom
PR4644  820R2F-GP  [R402H16]  152.88 100.5 0 bottom
PR4645  0R0402-PAD-1-GP  [0R0402-PAD]  152.27 103.34 270 bottom
PR4646  10R2F-L-GP  [R402H14]  152.09 87.95 90 bottom
PR4647  4K75R2F-1-GP  [R402H16]  152.07 100.3 0 bottom
PR4648  0R0402-PAD-1-GP  [0R0402-PAD]  152.27 104.16 270 bottom
PR4649  2K49R2F-GP  [R402H16]  151.28 100.3 0 bottom
PR4650  100R2F-L1-GP-U  [R402H14]  151.1 98.21 90 bottom
PR4651  4K87R2F-GP  [R402H16]  153.97 88.61 180 top
PR4652  21K5R2F-GP  [R402H16]  151.1 99.03 270 bottom
PR4653  NTC-100K-11-GP-U  [NTC-402H24-U]  143.05 89.5 270 bottom
PR4655  1K54R2F-GP  [R402H16]  151.94 89.88 270 bottom
PR4656  NTC-100K-11-GP-U  [NTC-402H24-U]  151.31 71.85 90 bottom
PR4657  2D2R2F-GP  [R402H16]  150.41 92.67 270 bottom
PR4658  97K6R2F-GP  [R402H16]  153.71 95.84 90 top
PR4659  24KR2F-GP  [R402H16]  153.8 94.17 90 top
PR4660  19K1R2F-GP  [R402H16]  153.72 96.66 90 top
PR4661  19K6R2F-GP  [R402H16]  150.16 89.88 90 bottom
PR4662  100KR2F-L1-GP  [R402H16]  153.72 95.01 90 top
PR4663  35K7R2F-GP  [R402H16]  153.08 97.48 90 top
PR4664  24KR2F-GP  [R402H16]  153.8 93.29 90 top
PR4665  49D9R2F-GP  [R402H16]  160.5 100.65 180 bottom
PR4666  0R0402-PAD-1-GP  [0R0402-PAD]  159.74 100.65 180 bottom
PR4667  10R2F-L-GP  [R402H14]  158.98 100.65 180 bottom
PR4668  100R2F-L1-GP-U  [R402H14]  158.21 100.65 0 bottom
PR4669  75R2F-2-GP  [R402H16]  153.36 105.81 0 top
PR4670  0R0402-PAD-1-GP  [0R0402-PAD]  162.23 98.64 270 bottom
PR4671  0R0402-PAD-1-GP  [0R0402-PAD]  159.84 91.43 180 top
PR4676  1KR2F-3-GP  [R402H16]  153.72 89.83 270 bottom
PR4677  10R2F-L-GP  [R402H14]  151.18 87.98 270 top
PR4678  4K87R2F-GP  [R402H16]  154.96 89.4 0 bottom
PR4679  75KR3F-GP  [R603H22]  154.13 87.62 270 bottom
PR4680  10R2F-L-GP  [R402H14]  154.71 102.91 0 bottom
PR4681  10R2F-L-GP  [R402H14]  163.75 95.34 180 bottom
PR4682  20KR2J-L2-GP  [R402H16]  161.09 92.04 90 top
PR4701  3D9R3-GP  [R603H22]  157.81 64.66 270 bottom
PR4702  2D2R2F-GP  [R402H16]  151.48 63.06 90 bottom
PR4703  2D2R5F-2-GP  [R805H24]  150.42 70.83 90 top
PR4704  0R0402-PAD-1-GP  [0R0402-PAD]  154.1 63.08 90 bottom
PR4711  3D9R3-GP  [R603H22]  157.4 81.04 270 bottom
PR4712  2D2R2F-GP  [R402H16]  152.22 77.69 270 bottom
PR4713  2D2R5F-2-GP  [R805H24]  149.02 85.31 90 top
PR4714  0R0402-PAD-1-GP  [0R0402-PAD]  154.35 78.58 0 bottom
PR4802  3D9R3-GP  [R603H22]  146.2 90.34 270 bottom
PR4803  2D2R2F-GP  [R402H16]  140.51 88.43 90 bottom
PR4804  2D2R5F-2-GP  [R805H24]  137.44 99.12 90 bottom
PR4808  0R0402-PAD-1-GP  [0R0402-PAD]  144.75 89.25 90 bottom
PR5013  2D2R3-1-U-GP  [R603H22]  152.32 56.2 90 bottom
PR5014  2D2R5F-2-GP  [R805H24]  146.23 57.5 90 top
PR5101  0R0603-PAD-1-GP-U  [0R0603-PAD-U]  44.75 9.36 90 top
PR5102  0R0402-PAD-1-GP  [0R0402-PAD]  44.12 3.01 180 bottom
PR5103  10KR2F-2-GP  [R402H16]  45.64 3.01 0 bottom
PR5104  10KR2F-2-GP  [R402H16]  44.88 3.01 180 bottom
PR5105  0R0402-PAD-1-GP  [0R0402-PAD]  53.08 2.12 90 bottom
PR5106  0R2J-2-GP  [R402H16]  47.17 3.01 0 bottom
PR5107  0R0402-PAD-1-GP  [0R0402-PAD]  47.98 4.39 90 bottom
PR5114  0R0402-PAD-1-GP  [0R0402-PAD]  44.63 10.96 90 bottom
PR5118  0R0402-PAD-1-GP  [0R0402-PAD]  40.44 10.89 0 top
PR5125  0R0402-PAD-1-GP  [0R0402-PAD]  31.16 10.89 180 top
PR5126  0R2J-2-GP  [R402H16]  30.4 10.89 180 top
PR5127  1MR2J-1-GP  [R402H16]  48.69 3.01 180 bottom
PR5201  88K7R2F-GP  [R402H16]  148.26 6.57 180 top
PR5202  2K55R2F-GP  [R402H16]  144.4 9.47 180 top
PR5203  100KR2F-L1-GP  [R402H16]  145.57 7.2 90 top
PR5204  10KR2F-2-GP  [R402H16]  146.02 9.44 0 top
PR5208  100KR2J-1-GP  [R402H16]  143.81 9.87 90 bottom
PR5209  0R0402-PAD-1-GP  [0R0402-PAD]  143.81 9.11 90 bottom
PR5210  0R0402-PAD-1-GP  [0R0402-PAD]  147.27 9.24 90 bottom
PR5401  47KR2J-2-GP  [R402H16]  56.82 11.4 0 top
PR5403  16K5R2F-2-GP  [R402H16]  45.39 12.79 0 top
PR5404  13K3R2F-L1-GP  [R402H16]  46.91 12.79 0 top
PR5405  0R0402-PAD-1-GP  [0R0402-PAD]  61.26 15.46 180 bottom
PR5406  0R0402-PAD-1-GP  [0R0402-PAD]  57.71 11.4 180 top
PR5408  0R0402-PAD-1-GP  [0R0402-PAD]  59.74 11.4 180 top
PR5409  47KR2J-2-GP  [R402H16]  39.29 95.6 180 bottom
PR5410  10KR2J-3-GP  [R402H16]  41.88 95.6 0 bottom
PR5417  0R0402-PAD-1-GP  [0R0402-PAD]  41.07 95.6 0 bottom
PR5419  29K4R2F-GP  [R402H16]  46.02 98.64 90 top
PR5420  13K7R2F-GP  [R402H16]  46.02 100.55 270 top
PT4702  SE330U2VDM-4-GP  [CT7343H83]  138.4 67.4 0 bottom
PT4703  SE33U25VM-11-GP  [CT7343H83]  166.29 84.17 0 bottom
PT4704  SE33U25VM-11-GP  [CT7343H83]  145.08 103.09 270 bottom
PT4705  SE330U2VDM-4-GP  [CT7343H83]  138.48 83.02 0 bottom
PT4801  ST330U2D5VBM-1-GP  [CT3528H79]  127.99 94.76 0 bottom
PU4301  SI7121DN-T1-GE3-GP  [PPAK-8P-2H45]  28.62 81.5 0 top
PU4302  SI7121DN-T1-GE3-GP  [PPAK-8P-2H45]  30.02 85.69 90 top
PU4303  SI7121DN-T1-GE3-GP  [PPAK-8P-2H45]  39.42 80.36 90 top
PU4304  SI7121DN-T1-GE3-GP  [PPAK-8P-2H45]  33.07 79.95 180 top
PU4305  SI7625DN-T1-GE3-GP  [PPAK-8P-2H45]  42.59 84.93 90 top
PU4306  SI7625DN-T1-GE3-GP  [PPAK-8P-2H45]  45.39 79.09 180 top
PU4307  SN74AUP1G04DRYR-GP  [XSON6H24]  21.89 78.45 90 bottom
PU4401  ISL88739HRZ-T-GP-U  [QFN32J4-G2D7H42]  143.18 34.66 0 bottom
PU4403  SI7121DN-T1-GE3-GP  [PPAK-8P-2H45]  155.73 45.81 0 bottom
PU4404  AON7410-GP  [PPAK-8P-3232H36]  144.09 48.81 90 top
PU4405  AON7410-GP  [PPAK-8P-3232H36]  145.64 44.37 270 top
PU4501  SY8286BRAC-GP  [QFN20Z3-G1D1H36]  161.11 58.46 270 bottom
PU4502  SY8288CRAC-GP  [QFN20Z3-G1D1H36]  99.67 105.88 0 top
PU4601  NCP81218MNTXG-GP  [LFQFN48J6-G4D6H40]  156.49 95.22 0 bottom
PU4701  NCP81382MNTXG-3-GP  [QFN36J4060-G2554H48]  153.08 67.28 0 bottom
PU4702  NCP81382MNTXG-3-GP  [QFN36J4060-G2554H48]  153.34 83.32 0 bottom
PU4801  NCP81382MNTXG-3-GP  [QFN36J4060-G2554H48]  141.98 94.56 0 bottom
PU5001  NCP81253MNTBG-1-GP  [LFDFN8G2-G1309H40]  153.21 53.69 90 bottom
PU5002  AON7410-GP  [PPAK-8P-3232H36]  147.83 59.5 90 bottom
PU5003  AON7410-GP  [PPAK-8P-3232H36]  146.3 55.03 270 bottom
PU5101  SY8288RAC-GP  [QFN20Z3-G1H36]  44.25 6.7 180 bottom
PU5102  APL5338XAI-TRG-GP  [MSOP10-G2D5H44]  40.44 12.03 90 bottom
PU5201  AOZ2262QI-10-GP-U  [QFN22G4-G2PH42]  145.59 5.05 180 bottom
PU5401  APL5930KAI-TRG-GP  [SOIC8-G3530H63]  51.1 13.94 90 bottom
PU5402  S-1339D15-M5001-GP  [SOT-23-5H52]  65.43 15.1 90 bottom
PU5403  APL5930KAI-TRG-GP  [SOIC8-G3530H63]  43.43 100.07 270 bottom
Q501  PJA138KA-GP  [SOT23DGS2D4H44]  34.39 13.1 180 bottom
Q1701  PJT138KA-GP  [SOT-363H44]  151.56 15.71 270 bottom
Q1702  2N7002KDW-1-GP  [SOT-363H44]  151.56 18.76 90 bottom
